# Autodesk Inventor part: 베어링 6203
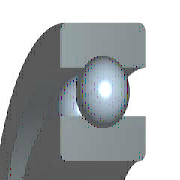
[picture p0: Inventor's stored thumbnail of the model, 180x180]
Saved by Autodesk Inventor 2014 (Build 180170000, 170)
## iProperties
IsCustomPart: 0
Created: 2009-02
Part Number: 베어링 6203
Material: 강, 연강
Description: 깊은 그루브 볼 베어링
Document SubType Name: Modeling
Standard: KS B 2023
Designer: 한국산업디자인학원 [http://gmhk.co.kr]
Standards Organization: KS
Language: ko-KR
Size Designation: 6203 - 17 x 40 x 12
Categories: <MemberInstance><Categories><Category DisplayName="샤프트 부품" InternalName="7f7aeb1f-a693-4053-b835-cee3144e0d98" Mnemonic="SHFT"><Category DisplayName="베어링" Inter
Density: 7.86 g/cm^3
Appearance: 크롬 - 광택
Mass: 58.8203 g
Surface Area: 64.3582 cm^2
Volume: 7.4835 cm^3
Author: pww
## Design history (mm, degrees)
sketch "스케치" dims "d0" = 5.98 (= -0.26 x WD + 0.26 x BD)
  geometry: L1 (3.01, 14.25)-(8.99, 14.25); L2 (6, 14.25)-(6, 11.26); L3 (6, 14.25)-(6, 17.24); L4 (3.778, 12.249)-(0, 12.249); L5 (0, 8.5)-(12, 8.5); L6 (3.778, 16.251)-(0, 16.251); L7 (0, 20)-(12, 20); L8 (12, 8.5)-(12, 12.249); L9 (8.222, 12.249)-(12, 12.249); L10 (8.222, 16.251)-(12, 16.251); L11 (12, 20)-(12, 16.251); L12 (-1.4, 0)-(8.4, 0) reference; L13 (0, -0.3)-(0, 5.3) reference
  constraints: 22 end point, 4 point on line, 2 collinear, 2 perpendicular, 2 symmetric about line, 1 midpoint, 1 parallel, 14 other
  dimensions: "d9" = 17 diameter of L5 L12 (= WD); "d11" = 40 diameter of L7 L12 (= BD); "d12" = 12 distance between parallel lines of L8 L13 (= KB); "d13" = 24.498 diameter of L9 L12 (= 0.326 x BD + 0.674 x WD)
revolve "본체" stored, may be unused: angle "d6" = 90 deg
revolve "볼" stored, may be unused: angle "d7" = 90 deg
pattern_circular "IDS_ARRAYBALL[SIMPL:T]" dims angle "d3" = 360 deg
body "Solid1"
fillet "모깎기1" dims "d1" = 0.6 (= KRS)
other parameters: "WD" = 17 [user parameter; used in 5 equation terms], "BD" = 40 [user parameter; used in 5 equation terms], "KB" = 12 [user parameter; used in 1 equation term], "KRS" = 0.6 [user parameter; used in 1 equation term], "d4" = 0, "d5" = 0, "d8" = 0, "d14" = 0, "d15" = 0, "BBA" = 0 [user parameter], "BC0" = 4750000 [user parameter], "BC" = 9560000 [user parameter], "WR" = 8.5 (= 0.5 x WD) [user parameter]
